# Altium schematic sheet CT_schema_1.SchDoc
size 455 x 431 mm
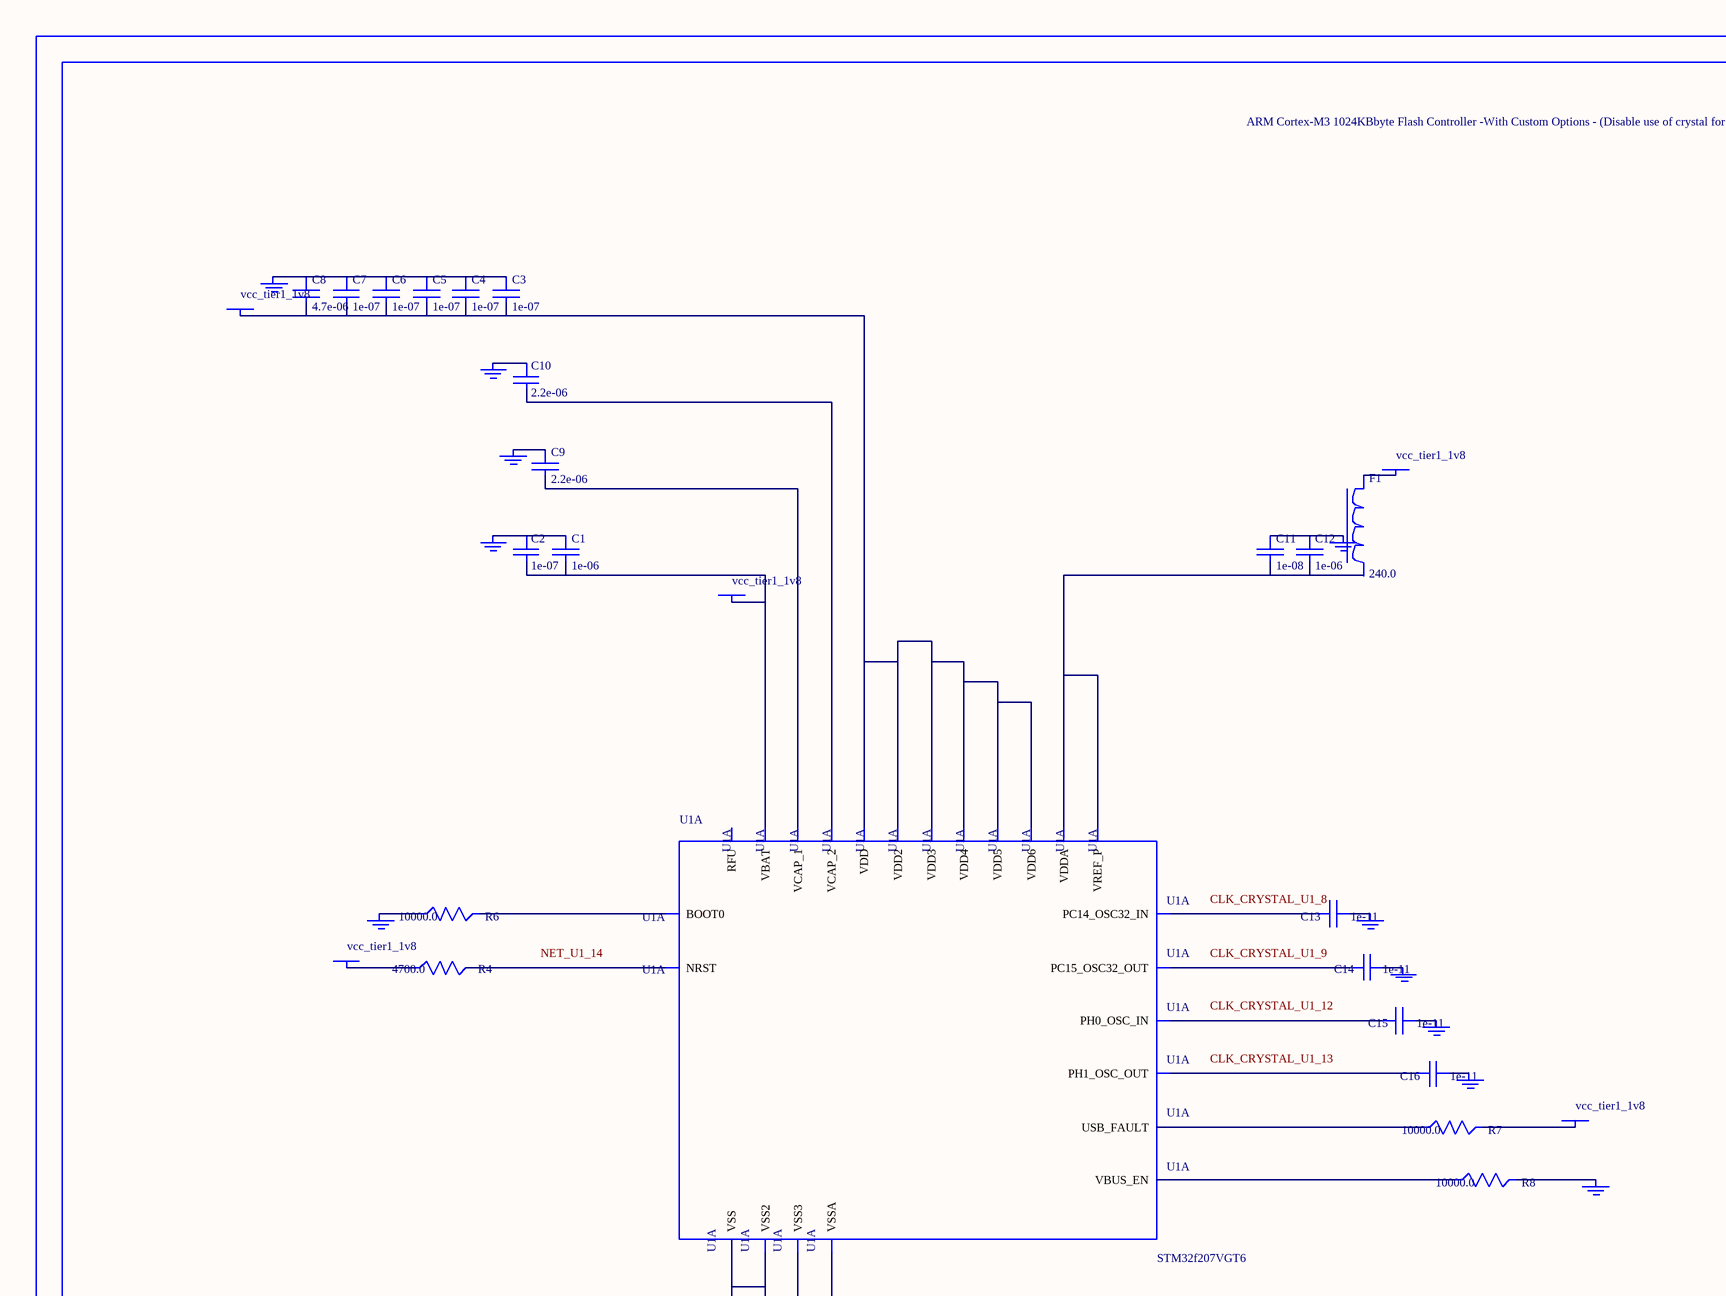
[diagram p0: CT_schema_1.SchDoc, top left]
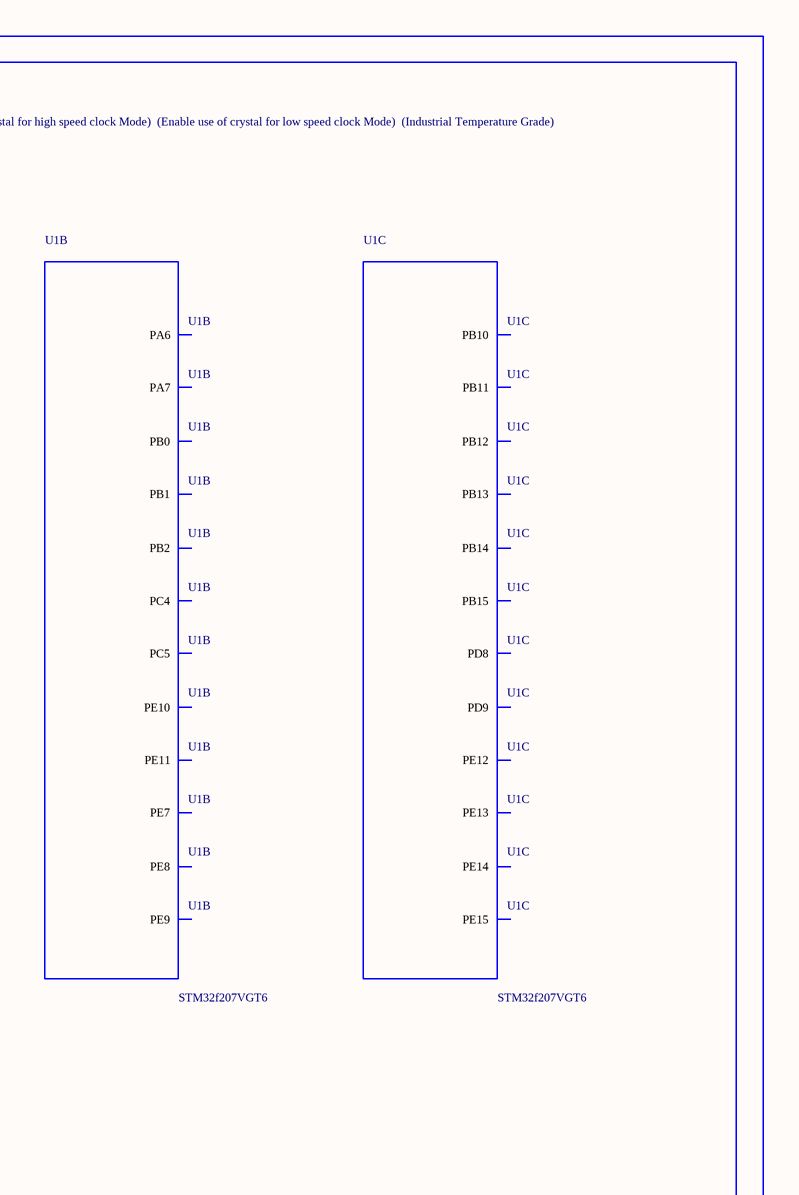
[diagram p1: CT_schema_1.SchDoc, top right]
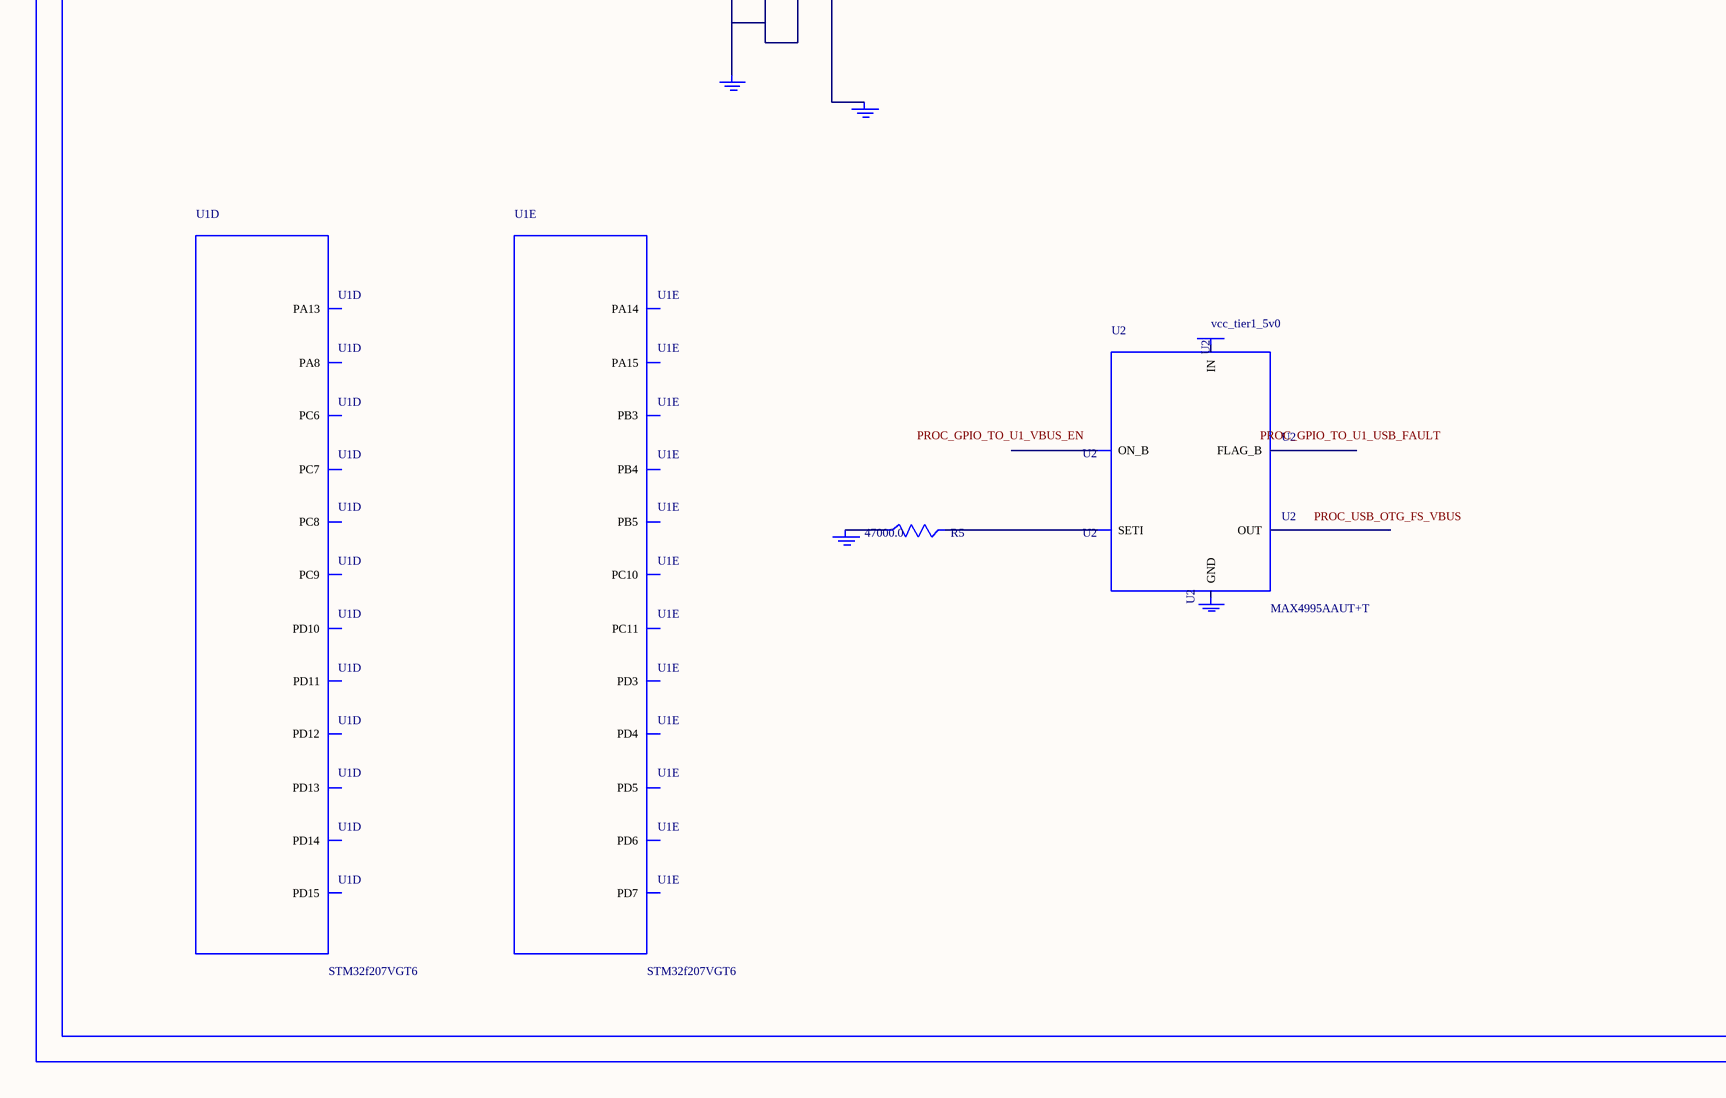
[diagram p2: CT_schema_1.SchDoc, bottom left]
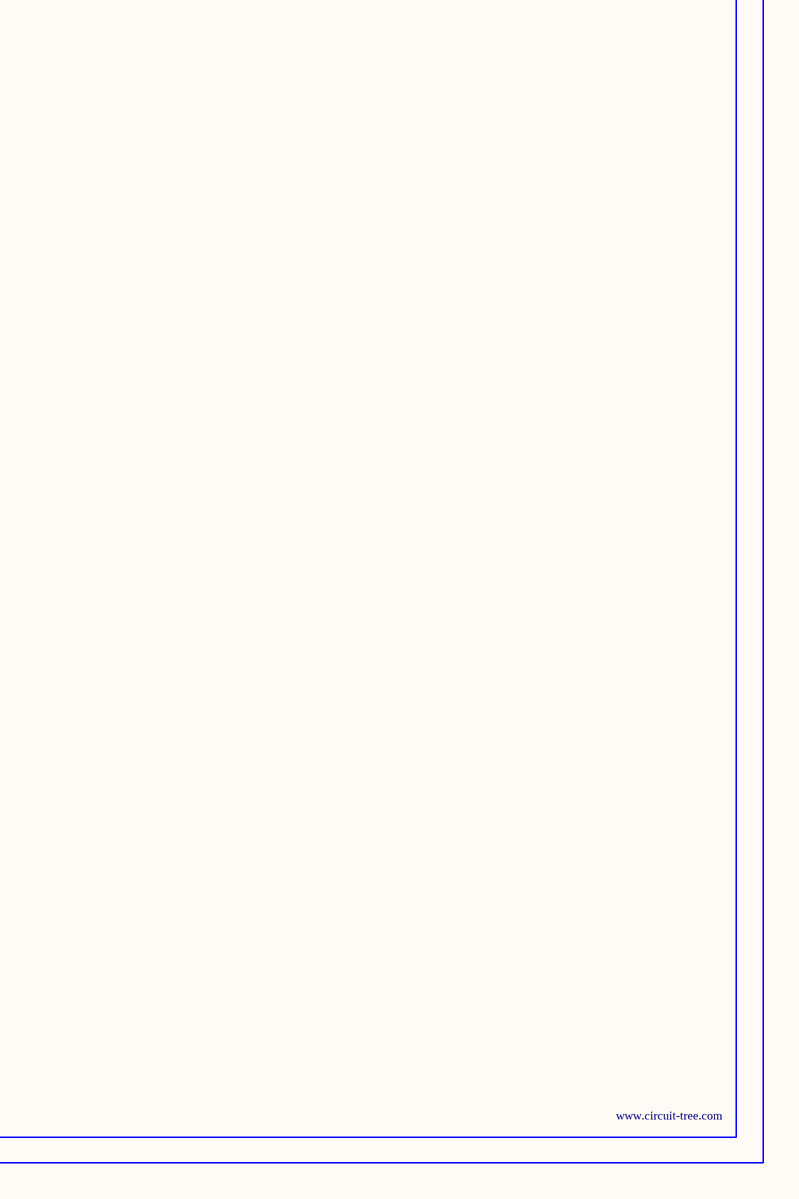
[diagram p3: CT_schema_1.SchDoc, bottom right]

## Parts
BORDER0  (no value)
C1  1e-06  [C0603]
C2  1e-07  [C0603]
C3  1e-07  [C0603]
C4  1e-07  [C0603]
C5  1e-07  [C0603]
C6  1e-07  [C0603]
C7  1e-07  [C0603]
C8  4.7e-06  [C0603]
C9  2.2e-06  [C0603]
C10  2.2e-06  [C0603]
C11  1e-08  [C0603]
C12  1e-06  [C0603]
C13  1e-11  [C0402]
C14  1e-11  [C0402]
C15  1e-11  [C0402]
C16  1e-11  [C0402]
F1  240.0  [L0603]
GND_INSTANCE_0_0  (no value)
GND_INSTANCE_0_1  (no value)
GND_INSTANCE_0_2  (no value)
GND_INSTANCE_0_3  (no value)
GND_INSTANCE_0_4  (no value)
GND_INSTANCE_0_5  (no value)
GND_INSTANCE_0_6  (no value)
GND_INSTANCE_0_7  (no value)
GND_INSTANCE_0_8  (no value)
GND_INSTANCE_0_9  (no value)
GND_INSTANCE_0_10  (no value)
GND_INSTANCE_0_11  (no value)
GND_INSTANCE_0_12  (no value)
GND_INSTANCE_0_13  (no value)
GND_INSTANCE_0_14  (no value)
POWER_INSTANCE_0_0  vcc_tier1_1v8
POWER_INSTANCE_0_1  vcc_tier1_1v8
POWER_INSTANCE_0_2  vcc_tier1_1v8
POWER_INSTANCE_0_3  vcc_tier1_1v8
POWER_INSTANCE_0_4  vcc_tier1_1v8
POWER_INSTANCE_0_5  vcc_tier1_5v0
R4  4700.0  [R0603]
R5  47000.0  [R0603]
R6  10000.0  [R0603]
R7  10000.0  [R0603]
R8  10000.0  [R0603]
U1  STM32f207VGT6  [LQFP100]  (parts A,B,C,D,E of 10)
U2  MAX4995AAUT+T  [SOT-23-6]

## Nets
NetC1_1: C1.1 C2.1 GND_INSTANCE_0_1.0(GND)
NetC1_2: C1.2 C2.2 POWER_INSTANCE_0_1.0(PWR) U1.6(VBAT)
NetC3_1: C3.1 C4.1 C5.1 C6.1 C7.1 C8.1 GND_INSTANCE_0_4.0(GND)
NetC3_2: C3.2 C4.2 C5.2 C6.2 C7.2 C8.2 POWER_INSTANCE_0_2.0(PWR) U1.11(VDD) U1.19(VDD2) U1.28(VDD3) U1.50(VDD4) U1.75(VDD5) U1.100(VDD6)
NetC9_1: C9.1 GND_INSTANCE_0_9.0(GND)
NetC9_2: C9.2 U1.49(VCAP_1)
NetC10_1: C10.1 GND_INSTANCE_0_10.0(GND)
NetC10_2: C10.2 U1.73(VCAP_2)
NetC11_1: C11.1 C12.1 GND_INSTANCE_0_8.0(GND)
NetC11_2: C11.2 C12.2 U1.21(VREF_P) U1.22(VDDA)
NetC13_1: C13.1 GND_INSTANCE_0_2.0(GND)
NetC13_2: C13.2 U1.8(PC14_OSC32_IN)
NetC14_1: C14.1 GND_INSTANCE_0_3.0(GND)
NetC14_2: C14.2 U1.9(PC15_OSC32_OUT)
NetC15_1: C15.1 GND_INSTANCE_0_5.0(GND)
NetC15_2: C15.2 U1.12(PH0_OSC_IN)
NetC16_1: C16.1 GND_INSTANCE_0_6.0(GND)
NetC16_2: C16.2 U1.13(PH1_OSC_OUT)
NetF1_1: F1.1 POWER_INSTANCE_0_3.0(PWR)
NetGND_INSTANCE_0_0_0: GND_INSTANCE_0_0.0(GND) R8.2
NetGND_INSTANCE_0_7_0: GND_INSTANCE_0_7.0(GND) U1.20(VSSA)
NetGND_INSTANCE_0_11_0: GND_INSTANCE_0_11.0(GND) R6.1
NetGND_INSTANCE_0_12_0: GND_INSTANCE_0_12.0(GND) U1.10(VSS) U1.27(VSS2) U1.74(VSS3)
NetGND_INSTANCE_0_13_0: GND_INSTANCE_0_13.0(GND) R5.1
NetPOWER_INSTANCE_0_0_0: POWER_INSTANCE_0_0.0(PWR) R7.2
NetPOWER_INSTANCE_0_4_0: POWER_INSTANCE_0_4.0(PWR) R4.1
NetR4_2: R4.2 U1.14(NRST)
NetR5_2: R5.2 U2.3(SETI)
NetR6_2: R6.2 U1.94(BOOT0)
NetR7_1: R7.1 U1.2(USB_FAULT)
NetR8_1: R8.1 U1.1(VBUS_EN)

Not connected (* = marked no-connect by the designer): F1 2; GND_INSTANCE_0_14 0(GND); POWER_INSTANCE_0_5 0(PWR); U1 31(PA6) 32(PA7) 33(PC4) 34(PC5) 35(PB0) 36(PB1) 37(PB2) 38(PE7) 39(PE8) 40(PE9) 41(PE10) 42(PE11) 43(PE12) 44(PE13) 45(PE14) 46(PE15) 47(PB10) 48(PB11) 51(PB12) 52(PB13) 53(PB14) 54(PB15) 55(PD8) 56(PD9) 57(PD10) 58(PD11) 59(PD12) 60(PD13) 61(PD14) 62(PD15) 63(PC6) 64(PC7) 65(PC8) 66(PC9) 67(PA8) 72(PA13) 76(PA14) 77(PA15) 78(PC10) 79(PC11) 84(PD3) 85(PD4) 86(PD5) 87(PD6) 88(PD7) 89(PB3) 90(PB4) 91(PB5) 99(RFU); U2 1(OUT) 2(GND) 4(ON_B) 5(IN) 6(FLAG_B)

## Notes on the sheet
- Labels drawn without touching a wire or pin: CLK_CRYSTAL_U1_8, CLK_CRYSTAL_U1_9, CLK_CRYSTAL_U1_12, CLK_CRYSTAL_U1_13, NET_U1_14, PROC_GPIO_TO_U1_USB_FAULT, PROC_GPIO_TO_U1_VBUS_EN, PROC_USB_OTG_FS_VBUS

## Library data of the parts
BORDER0 = BORDER_PAGE0
C1 C12 = C0603C105K3RACTU
C2-C7 = 06035C104K4Z2A
C8 = GRM188R6YA475KE15D
C9 C10 = C0603C225K8RACTU
C11 = 06035C103K4Z2A
C13-C16 = C0402C100K3GACTU
F1 = Z0603C241ASMST
GND_INSTANCE_0_0-GND_INSTANCE_0_14 = GND
POWER_INSTANCE_0_0-POWER_INSTANCE_0_5 = PWR
R4 = RC0603JR-074K7L
R5 = RC0603JR-0747KL
R6-R8 = RC0603JR-0710KL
